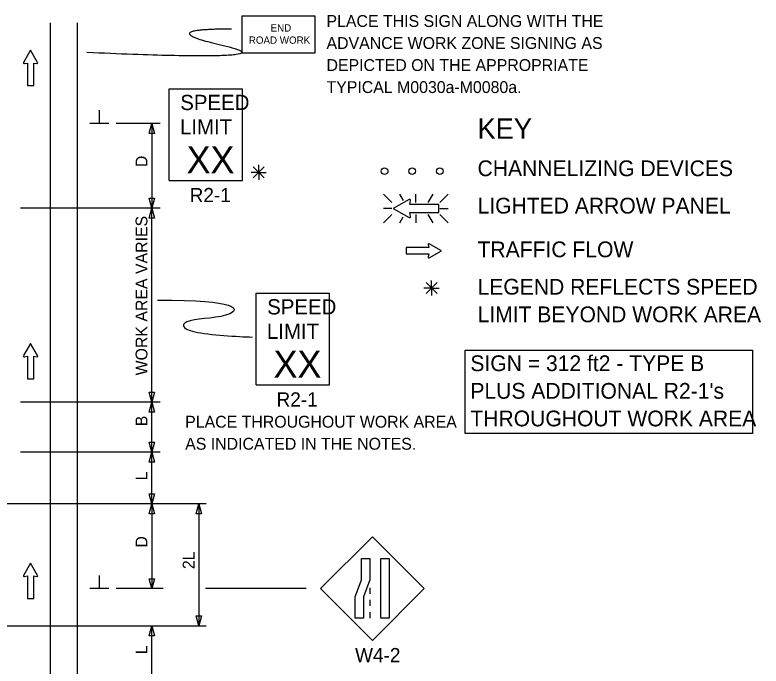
# Model space of a CAD drawing. Extents: x 16732 to 18478, y 5523 to 6928.
# Drawn here: x 16983.9 to 17424, y 6539.6 to 6923.9 of the extents above; entities that cross this region are included whole.
import ezdxf

# ---------------------------------------------------------------- set-up
doc = ezdxf.new("R2010")
doc.units = 0
for name, color, linetype in [('MT_SCRATCH_LEVEL_E', 7, 'Continuous'), ('PAVT_EDGE_EX', 7, 'Continuous'), ('TRAFFIC_SIGNS_PR', 7, 'Continuous'), ('TYPICAL_TEXT_DIMEN_EX', 7, 'Continuous'), ('TYPICAL_TEXT_DIMEN_PR', 7, 'Continuous')]:
    doc.layers.add(name, color=color, linetype=linetype)

msp = doc.modelspace()

# ---------------------------------------------------------------- linework, layer by layer
at = {"layer": 'MT_SCRATCH_LEVEL_E'}
for p, q in [((16993.16, 6903.1), (16989.05, 6895.86)), ((16997.31, 6895.86), (16993.16, 6903.1)), ((16989.53, 6895.17), (16991.31, 6895.49)), ((16991.31, 6895.49), (16991.31, 6882.23)), ((16995.05, 6882.23), (16995.05, 6895.49)), ((16995.05, 6895.49), (16996.83, 6895.17)), ((16991.31, 6882.23), (16995.05, 6882.23)), ((17227.93, 6786.61), (17214.67, 6786.61)), ((17214.67, 6786.61), (17214.67, 6782.86)), ((17227.62, 6788.38), (17227.93, 6786.61)), ((17235.54, 6784.76), (17228.3, 6788.87)), ((17214.67, 6782.86), (17227.93, 6782.86)), ((17227.93, 6782.86), (17227.62, 6781.09)), ((17228.3, 6780.61), (17235.54, 6784.76)), ((16993.16, 6730.05), (16989.05, 6722.81)), ((16997.31, 6722.81), (16993.16, 6730.05)), ((16989.53, 6722.12), (16991.31, 6722.44)), ((16991.31, 6722.44), (16991.31, 6709.18)), ((16995.05, 6709.18), (16995.05, 6722.44)), ((16995.05, 6722.44), (16996.83, 6722.12)), ((16991.31, 6709.18), (16995.05, 6709.18)), ((16993.16, 6600.4), (16989.05, 6593.16)), ((16997.31, 6593.16), (16993.16, 6600.4)), ((16989.53, 6592.48), (16991.31, 6592.79)), ((16991.31, 6592.79), (16991.31, 6579.54)), ((16995.05, 6579.54), (16995.05, 6592.79)), ((16995.05, 6592.79), (16996.83, 6592.48)), ((16991.31, 6579.54), (16995.05, 6579.54))]:
    msp.add_line(p, q, dxfattribs=at)
for centre, start, end in [((16989.46, 6895.63), 150.4248, 279.9638), ((16996.9, 6895.63), 260.0362, 29.7731), ((17228.07, 6788.46), 60.4248, 189.9638), ((17228.07, 6781.02), 170.0362, 299.7731), ((16989.46, 6722.58), 150.4248, 279.9638), ((16996.9, 6722.58), 260.0362, 29.7731), ((16989.46, 6592.94), 150.4248, 279.9638), ((16996.9, 6592.94), 260.0362, 29.7731)]:
    msp.add_arc(centre, 0.463, start, end, dxfattribs=at)
at = {"layer": 'PAVT_EDGE_EX'}
for p, q in [((17004.63, 6919.19), (17004.63, 6002.83)), ((17020.63, 6919.19), (17020.63, 6002.83))]:
    msp.add_line(p, q, dxfattribs=at)
at = {"layer": 'TRAFFIC_SIGNS_PR'}
for p, q in [((17074.95, 6880.28), (17118.15, 6880.28)), ((17074.95, 6826.28), (17074.95, 6880.28)), ((17118.15, 6826.28), (17118.15, 6880.28)), ((17074.95, 6826.28), (17118.15, 6826.28)), ((17201.35, 6818.14), (17206.28, 6813.21)), ((17213.11, 6814.32), (17210.91, 6818.14)), ((17220.43, 6813.21), (17220.43, 6818.14)), ((17227.67, 6813.21), (17230.52, 6818.14)), ((17234.58, 6813.21), (17239.52, 6818.14)), ((17206.28, 6809.65), (17201.35, 6809.65)), ((17234.58, 6809.65), (17239.52, 6809.65)), ((17201.35, 6801.16), (17206.28, 6806.09)), ((17210.86, 6801.16), (17212.97, 6804.82)), ((17220.43, 6806.09), (17220.43, 6801.16)), ((17230.56, 6801.16), (17227.71, 6806.09)), ((17234.58, 6806.09), (17239.52, 6801.16)), ((17126.21, 6759.66), (17169.41, 6759.66)), ((17126.21, 6705.66), (17126.21, 6759.66)), ((17169.41, 6705.66), (17169.41, 6759.66)), ((17126.21, 6705.66), (17169.41, 6705.66)), ((17194.71, 6615.88), (17164.16, 6585.33)), ((17225.26, 6585.33), (17194.71, 6615.88)), ((17164.16, 6585.33), (17194.71, 6554.79)), ((17193.31, 6585.89), (17193.31, 6582.29)), ((17194.71, 6554.79), (17225.26, 6585.33)), ((17193.31, 6578.69), (17193.31, 6575.09)), ((17193.31, 6571.49), (17193.31, 6567.89))]:
    msp.add_line(p, q, dxfattribs=at)
for points in [[(17117.81, 6901.54), (17161.01, 6901.54), (17161.01, 6923.14), (17117.81, 6923.14)], [(17193.31, 6603.04), (17193.31, 6590.46), (17189.54, 6580.46), (17189.54, 6567.89), (17184.49, 6567.89), (17184.49, 6580.46), (17188.25, 6590.46), (17188.25, 6603.04)], [(17204.71, 6603.04), (17204.71, 6567.89), (17199.66, 6567.89), (17199.66, 6603.04)]]:
    msp.add_lwpolyline(points, close=True, dxfattribs=at)
for points in [[(17216.36, 6814.93), (17207.07, 6809.65), (17216.36, 6804.33)], [(17217.24, 6804.96), (17216.83, 6807.22), (17233.85, 6807.22), (17233.85, 6812.03), (17216.83, 6812.03), (17217.24, 6814.31)]]:
    msp.add_lwpolyline(points, dxfattribs=at)
for centre in [(17201.91, 6831.68), (17218.21, 6831.68), (17234.51, 6831.68)]:
    msp.add_circle(centre, 2, dxfattribs=at)
for centre, radius, start, end in [((17216.65, 6814.4), 0.598, 350.7308, 118.8916), ((17216.65, 6804.85), 0.597, 241.4833, 9.9593)]:
    msp.add_arc(centre, radius, start, end, dxfattribs=at)
msp.add_open_spline([(17111.64, 6915.52), (17064.41, 6915.52), (17149.43, 6896.18), (17026.33, 6901.67)], degree=2, dxfattribs=at)
at = {"layer": 'TYPICAL_TEXT_DIMEN_EX'}
msp.add_lwpolyline([(17249.52, 6726.09), (17418.98, 6726.09), (17418.98, 6676.9), (17249.52, 6676.9)], close=True, dxfattribs=at)
at = {"layer": 'TYPICAL_TEXT_DIMEN_PR'}
for p, q in [((17033.76, 6859.85), (17033.76, 6867.64)), ((17039.38, 6859.85), (17028.13, 6859.85)), ((17069.63, 6859.85), (17043.63, 6859.85)), ((17063.06, 6853.99), (17064.63, 6859.85)), ((17064.63, 6859.85), (17064.63, 6809.85)), ((17064.63, 6859.85), (17066.2, 6853.99)), ((17064.63, 6853.99), (17063.06, 6853.99)), ((17066.2, 6853.99), (17064.63, 6853.99)), ((17130.88, 6834.18), (17124.5, 6827.8)), ((17124.51, 6834.18), (17130.88, 6827.8)), ((17127.69, 6830.99), (17127.69, 6835.44)), ((17127.69, 6830.99), (17123.16, 6830.99)), ((17127.69, 6830.99), (17130.88, 6830.99)), ((17127.69, 6830.99), (17132.17, 6830.99)), ((17127.69, 6830.99), (17127.69, 6826.49)), ((17064.63, 6809.85), (17063.06, 6815.71)), ((17063.06, 6815.71), (17064.63, 6815.71)), ((17064.63, 6815.71), (17066.2, 6815.71)), ((17066.2, 6815.71), (17064.63, 6809.85)), ((17069.63, 6809.85), (16987.24, 6809.85)), ((17063.06, 6803.99), (17064.63, 6809.85)), ((17064.63, 6695.32), (17064.63, 6809.85)), ((17064.63, 6809.85), (17066.2, 6803.99)), ((17064.63, 6803.99), (17063.06, 6803.99)), ((17066.2, 6803.99), (17064.63, 6803.99)), ((17226.5, 6765.93), (17232.88, 6759.55)), ((17232.88, 6765.93), (17226.5, 6759.55)), ((17229.69, 6762.74), (17229.69, 6767.19)), ((17229.69, 6762.74), (17225.16, 6762.74)), ((17229.69, 6762.74), (17232.88, 6762.74)), ((17229.69, 6762.74), (17234.17, 6762.74)), ((17229.69, 6762.74), (17229.69, 6758.24)), ((17064.63, 6695.32), (17063.06, 6701.18)), ((17063.06, 6701.18), (17064.63, 6701.18)), ((17064.63, 6701.18), (17066.2, 6701.18)), ((17066.2, 6701.18), (17064.63, 6695.32)), ((17069.63, 6695.32), (16987.24, 6695.32)), ((17063.06, 6689.45), (17064.63, 6695.32)), ((17064.63, 6665.89), (17064.63, 6695.32)), ((17064.63, 6695.32), (17066.2, 6689.45)), ((17064.63, 6689.45), (17063.06, 6689.45)), ((17066.2, 6689.45), (17064.63, 6689.45)), ((17064.63, 6665.89), (17063.06, 6671.75)), ((17063.06, 6671.75), (17064.63, 6671.75)), ((17064.63, 6671.75), (17066.2, 6671.75)), ((17066.2, 6671.75), (17064.63, 6665.89)), ((17069.63, 6665.89), (16987.24, 6665.89)), ((17063.06, 6660.03), (17064.63, 6665.89)), ((17064.63, 6635.32), (17064.63, 6665.89)), ((17064.63, 6665.89), (17066.2, 6660.03)), ((17064.63, 6660.03), (17063.06, 6660.03)), ((17066.2, 6660.03), (17064.63, 6660.03)), ((17064.63, 6635.32), (17063.06, 6641.19)), ((17063.06, 6641.19), (17064.63, 6641.19)), ((17064.63, 6641.19), (17066.2, 6641.19)), ((17066.2, 6641.19), (17064.63, 6635.32)), ((17096.68, 6635.32), (16965.53, 6635.32)), ((17063.06, 6629.46), (17064.63, 6635.32)), ((17064.63, 6635.32), (17064.63, 6585.32)), ((17064.63, 6635.32), (17066.2, 6629.46)), ((17090.87, 6629.46), (17092.44, 6635.32)), ((17092.44, 6635.32), (17094.01, 6629.46)), ((17092.44, 6635.32), (17092.44, 6563.32)), ((17064.63, 6629.46), (17063.06, 6629.46)), ((17066.2, 6629.46), (17064.63, 6629.46)), ((17092.44, 6629.46), (17090.87, 6629.46)), ((17094.01, 6629.46), (17092.44, 6629.46)), ((17033.76, 6585.32), (17033.76, 6593.11)), ((17064.63, 6585.32), (17063.06, 6591.19)), ((17063.06, 6591.19), (17064.63, 6591.19)), ((17064.63, 6591.19), (17066.2, 6591.19)), ((17066.2, 6591.19), (17064.63, 6585.32)), ((17092.44, 6590.19), (17092.44, 6586.43)), ((17039.38, 6585.32), (17028.13, 6585.32)), ((17071.43, 6585.32), (17043.63, 6585.32)), ((17155.65, 6585.32), (17096.37, 6585.32)), ((17092.44, 6563.32), (17090.87, 6569.19)), ((17090.87, 6569.19), (17092.44, 6569.19)), ((17092.44, 6569.19), (17094.01, 6569.19)), ((17094.01, 6569.19), (17092.44, 6563.32)), ((16965.53, 6563.32), (17096.68, 6563.32)), ((17063.06, 6557.46), (17064.63, 6563.32)), ((17064.63, 6532.76), (17064.63, 6563.32)), ((17064.63, 6563.32), (17066.2, 6557.46)), ((17064.63, 6557.46), (17063.06, 6557.46)), ((17066.2, 6557.46), (17064.63, 6557.46))]:
    msp.add_line(p, q, dxfattribs=at)
for points, degree in [([(17288.16, 6804.54), (17288.17, 6804.54), (17288.18, 6804.54), (17288.18, 6804.54)], 2), ([(17067.94, 6755.64), (17116.41, 6755.64), (17116.41, 6744.88), (17081.49, 6744.88), (17081.49, 6735.83), (17115.7, 6734.07), (17123.99, 6733.78)], 3)]:
    msp.add_open_spline(points, degree=degree, dxfattribs=at)

# ---------------------------------------------------------------- texts
at = {"layer": 'TRAFFIC_SIGNS_PR'}
for s, height, p in [('PLACE THIS SIGN ALONG WITH THE', 7, (17167.68, 6916.8)), ('END', 4.31, (17134.69, 6914.06)), ('ROAD WORK', 4.31, (17121.87, 6906.87)), ('ADVANCE WORK ZONE SIGNING AS', 7, (17167.68, 6903.8)), ('DEPICTED ON THE APPROPRIATE', 7, (17167.68, 6890.8)), ('TYPICAL M0030a-M0080a.', 7, (17167.68, 6877.8)), ('SPEED', 9, (17081.44, 6867.74)), ('LIMIT', 9, (17081.26, 6853.34)), ('XX', 15.785, (17085.2, 6830.5)), ('R2-1', 8.37, (17086.96, 6813.4)), ('SPEED', 9, (17132.7, 6747.13)), ('LIMIT', 9, (17132.52, 6732.73)), ('XX', 15.785, (17136.46, 6709.88)), ('R2-1', 8.37, (17138.22, 6692.79)), ('PLACE THROUGHOUT WORK AREA', 7, (17084.34, 6680.31)), ('AS INDICATED IN THE NOTES.', 7, (17084.34, 6667.31)), ('W4-2', 8.37, (17184.54, 6541.92))]:
    msp.add_text(s, height=height, dxfattribs=at).set_placement(p)
at = {"layer": 'TYPICAL_TEXT_DIMEN_EX'}
for s, height, p in [('KEY', 12, (17256.75, 6850.79)), ('CHANNELIZING DEVICES', 9.3, (17256.75, 6828.74)), ('LIGHTED ARROW PANEL', 9.3, (17256.75, 6806.69)), ('TRAFFIC FLOW', 9.3, (17256.75, 6780.89)), ('LEGEND REFLECTS SPEED', 9.3, (17256.75, 6758.84)), ('LIMIT BEYOND WORK AREA', 9.3, (17256.75, 6742.54)), ('SIGN = 312 ft2 - TYPE B', 9.3, (17252.53, 6713.69)), ("PLUS ADDITIONAL R2-1's", 9.3, (17252.53, 6697.39)), ('THROUGHOUT WORK AREA', 9.3, (17252.53, 6681.09))]:
    msp.add_text(s, height=height, dxfattribs=at).set_placement(p)
at = {"layer": 'TYPICAL_TEXT_DIMEN_PR'}
for s, p in [('D', (17062.08, 6834.07)), ('WORK AREA VARIES', (17062.08, 6711.17)), ('B', (17062.08, 6681.15)), ('L', (17062.08, 6649.18)), ('D', (17062.08, 6609.54)), ('2L', (17089.88, 6596.83)), ('L', (17062.08, 6546.62))]:
    msp.add_text(s, height=7, rotation=90, dxfattribs=at).set_placement(p)

doc.saveas('drawing.dxf')
